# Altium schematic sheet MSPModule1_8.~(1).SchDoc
size 297 x 209 mm; PageSetup: Record=PageOptions¦CenterHorizontal=True¦CenterVertical=True¦PrintScale=0.99¦XCorrection=1.00¦YCorrection=1.00¦PrintKind=0¦BorderSize=5000000¦LeftOffset=0¦BottomOffset=0¦Orientation=2¦PaperLength=1000¦PaperWidth=1000¦Scale=100¦PaperSource=7¦PrintQuality=-3¦MediaType=1¦DitherType=10¦PrintScaleMode=1¦PaperKind=A4¦PaperIndex=9
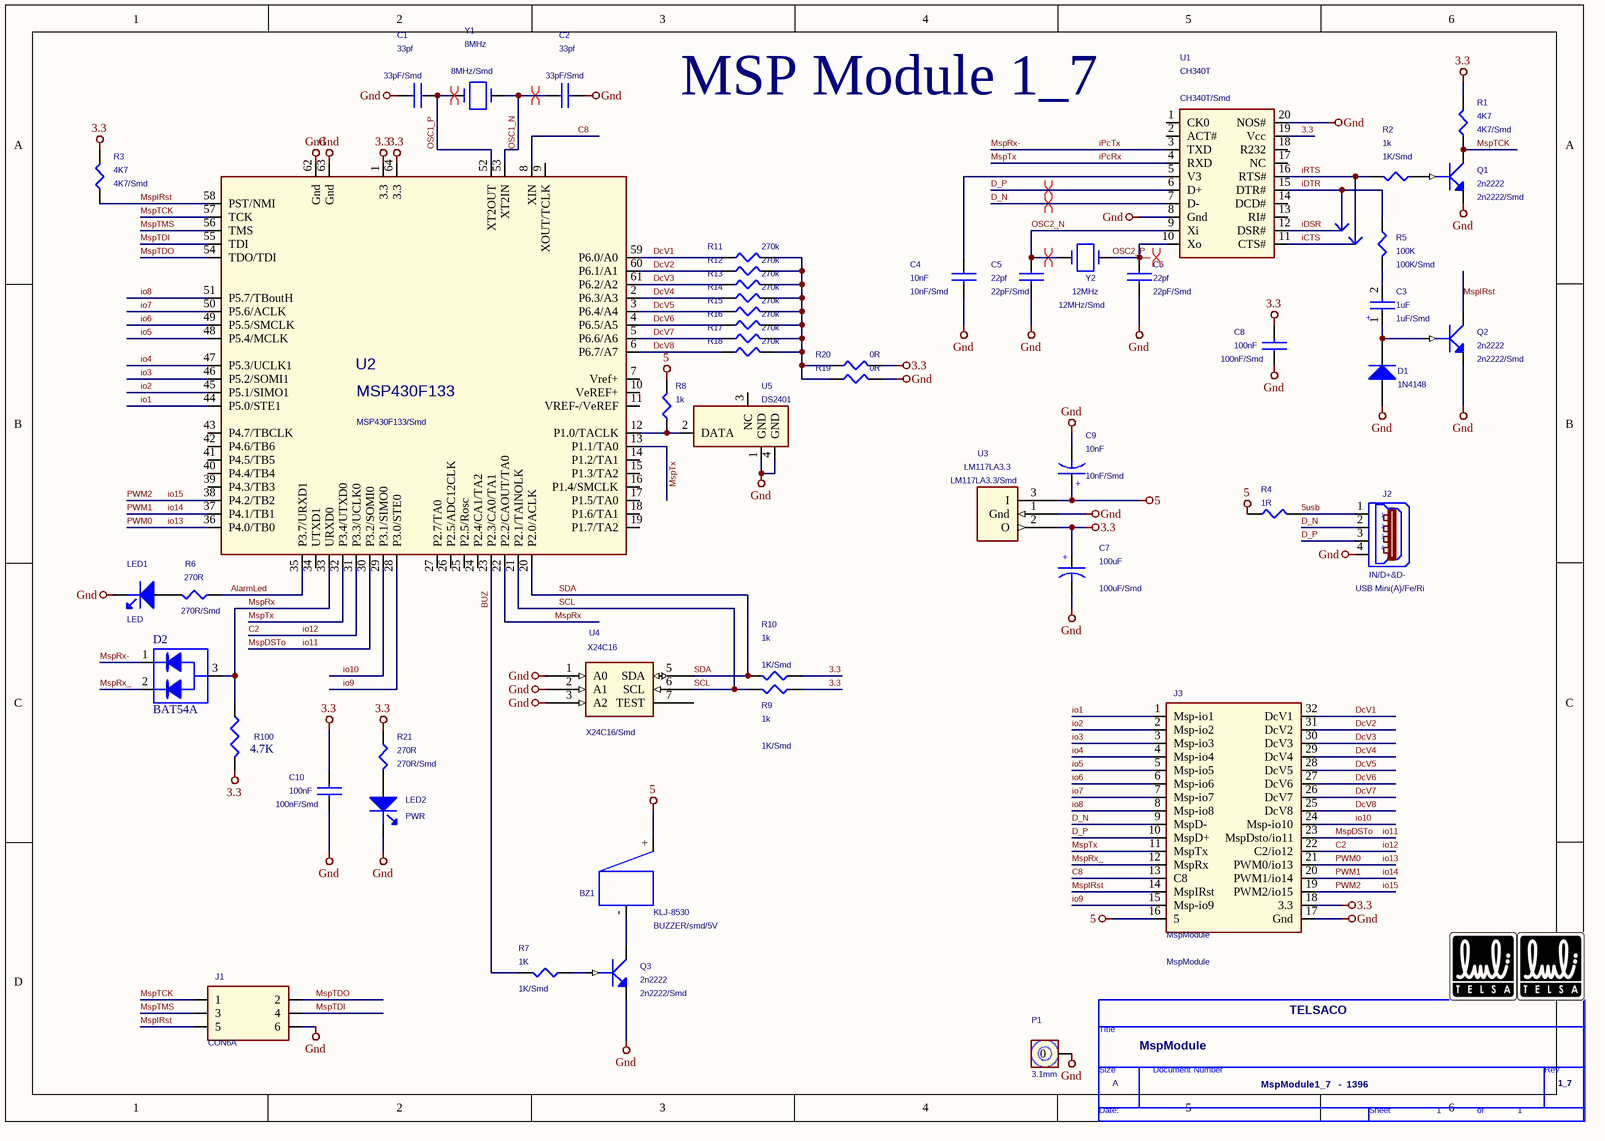
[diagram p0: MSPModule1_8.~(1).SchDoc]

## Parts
*  Page Count: 1  Page Size: A  Title: MspModule  RevCode: 1_7  Doc: MspModule1_7   -  1396  OrgName: TELSACO  (hidden comment: TitleBlock0)  (graphical)
BZ1  KLJ-8530  PART: BUZZER/smd/5V  [BUZZER SMD]
C1  33pf  PART: 33pF/Smd  [0805T]
C2  33pf  PART: 33pF/Smd  [0805T]
C3  1uF  PART: 1uF/Smd  [0805T]
C4  10nF  PART: 10nF/Smd  [0805T]
C5  22pf  PART: 22pF/Smd  [0805T]
C6  22pf  PART: 22pF/Smd  [0805T]
C7  100uF  PART: 100uF/Smd  [1210T]
C8  100nF  PART: 100nF/Smd  [0805T]
C9  10nF  PART: 10nF/Smd  [0805T]
C10  100nF  PART: 100nF/Smd  [0805T]
D1  1N4148  [0805-D]
D2  BAT54A  [SOT23]
J1  CON6A  [IDC6]
J2  IN/D+&D-  PART: USB Mini(A)/Fe/Ri  [MINI USB]
J3  MspModule  [MSPMODULE_2MM]
LED1  LED  [0805-D]
LED2  PWR  [0805-D]
P1  3.1mm  [SCREW3.1]
Q1  2n2222  PART: 2n2222/Smd  [SOT23_3]
Q2  2n2222  PART: 2n2222/Smd  [SOT23_3]
Q3  2n2222  PART: 2n2222/Smd  [SOT23_3]
R1  4K7  PART: 4K7/Smd  [0805R]
R2  1k  PART: 1K/Smd  [0805R]
R3  4K7  PART: 4K7/Smd  [0805R]
R4  1R  [0805R]
R5  100K  PART: 100K/Smd  [0805R]
R6  270R  PART: 270R/Smd  [0805R]
R7  1K  PART: 1K/Smd  [0805R]
R8  1k  [0805R]
R9  1k  PART: 1K/Smd  [0805R]
R10  1k  PART: 1K/Smd  [0805R]
R11  270k  [0805R]
R12  270k  [0805R]
R13  270k  [0805R]
R14  270k  [0805R]
R15  270k  [0805R]
R16  270k  [0805R]
R17  270k  [0805R]
R18  270k  [0805R]
R19  0R  [0805R]
R20  0R  [0805R]
R21  270R  PART: 270R/Smd  [0805R]
R100  4.7K  [0805R]
Telsa  ARM Telsa  [Arm2-Top]  (value not drawn)
Telsa1  ARM Telsa  [ARM1]  (value not drawn)
U1  CH340T  PART: CH340T/Smd  [SSOP20]
U2  MSP430F133  PART: MSP430F133/Smd  [MSP64]
U3  LM117LA3.3  PART: LM117LA3.3/Smd  [LM117]
U4  X24C16  PART: X24C16/Smd  [SO-8]
U5  DS2401  [DS2401]
Y1  8MHz  PART: 8MHz/Smd  [CRYSTAL-SMD]
Y2  12MHz  PART: 12MHz/Smd  [CRYSTAL-SMD]

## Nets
3.3: C7.1 C8.2 C10.2 J3.18(3.3) R1.2 R3.2 R9.1 R10.1 R20.2 R21.2 R100.2 U1.19(Vcc) U2.1(3.3) U2.64(3.3) U3.2(O) U4.8(3.3)
5: BZ1.+ C9.1 J3.16(5) R4.1 R8.2 U3.3(I)
Gnd: C1.2 C2.2 C4.2 C5.2 C6.2 C7.2 C8.1 C9.2 C10.1 D1.A J1.6 J2.4(GND) J2.5(GND) J3.17(Gnd) LED1.2 LED2.2 P1.0 Q1.2 Q2.2 Q3.2 R19.2 U1.8(Gnd) U1.20(NOS#) U2.62(Gnd) U2.63(Gnd) U3.1(Gnd) U4.1(A0) U4.2(A1) U4.3(A2) U4.4(Gnd) U5.1(GND) U5.4(GND)
5usb: J2.1(5V) R4.2
AlarmLed: R6.2 U2.35(P3.7/URXD1)
BUZ: R7.2 U2.23(P2.3/CA0/TA1)
C2: J3.22(C2/io12) U2.31(P3.3/UCLK0)  [also labelled io12]
C8: J3.13(C8) U2.8(XIN)
D_N: J2.2(D-) J3.9(MspD-) U1.7(D-)
D_P: J2.3(D+) J3.10(MspD+) U1.6(D+)
DcV1: J3.32(DcV1) R11.1 U2.59(P6.0/A0)
DcV2: J3.31(DcV2) R12.1 U2.60(P6.1/A1)
DcV3: J3.30(DcV3) R13.1 U2.61(P6.2/A2)
DcV4: J3.29(DcV4) R14.1 U2.2(P6.3/A3)
DcV5: J3.28(DcV5) R15.1 U2.3(P6.4/A4)
DcV6: J3.27(DcV6) R16.1 U2.4(P6.5/A5)
DcV7: J3.26(DcV7) R17.1 U2.5(P6.6/A6)
DcV8: J3.25(DcV8) R18.1 U2.6(P6.7/A7)
iCTS: R2.2 U1.11(CTS#) U1.16(RTS#)  [also labelled iRTS]
iDSR: R5.1 U1.12(DSR#) U1.15(DTR#)  [also labelled iDTR]
io1: J3.1(Msp-io1) U2.44(P5.0/STE1)
io2: J3.2(Msp-io2) U2.45(P5.1/SIMO1)
io3: J3.3(Msp-io3) U2.46(P5.2/SOMI1)
io4: J3.4(Msp-io4) U2.47(P5.3/UCLK1)
io5: J3.5(Msp-io5) U2.48(P5.4/MCLK)
io6: J3.6(Msp-io6) U2.49(P5.5/SMCLK)
io7: J3.7(Msp-io7) U2.50(P5.6/ACLK)
io8: J3.8(Msp-io8) U2.51(P5.7/TBoutH)
io9: J3.15(Msp-io9) U2.28(P3.0/STE0)
io10: J3.24(Msp-io10) U2.29(P3.1/SIMO0)
io11: J3.23(MspDsto/io11) U2.30(P3.2/SOMI0)  [also labelled MspDSTo]
io13: J3.21(PWM0/io13) U2.36(P4.0/TB0)  [also labelled PWM0]
io14: J3.20(PWM1/io14) U2.37(P4.1/TB1)  [also labelled PWM1]
io15: J3.19(PWM2/io15) U2.38(P4.2/TB2)  [also labelled PWM2]
iPcRx: J3.11(MspTx) U1.4(RXD) U2.13(P1.1/TA0) U2.32(P3.4/UTXD0)  [also labelled MspTx]
iPcTx: D2.1 U1.3(TXD)  [also labelled MspRx-]
MspIRst: J1.5 J3.14(MspIRst) Q2.3 R3.1 U2.58(PST/NMI)
MspRx: D2.3 R100.1 U2.22(P2.2/CAOUT/TA0) U2.33(URXD0)
MspRx_: D2.2 J3.12(MspRx)
MspTCK: J1.1 Q1.3 R1.1 U2.57(TCK)
MspTDI: J1.4 U2.55(TDI)
MspTDO: J1.2 U2.54(TDO/TDI)
MspTMS: J1.3 U2.56(TMS)
OSC1_N: C2.1 U2.53(XT2IN) Y1.1
OSC1_P: C1.1 U2.52(XT2OUT) Y1.2
OSC2_N: C5.1 U1.9(Xi) Y2.2
OSC2_P: C6.1 U1.10(Xo) Y2.1
SCL: R9.2 U2.21(P2.1/TAINOLK) U4.6(SCL)
SDA: R10.2 U2.20(P2.0/ACLK) U4.5(SDA)
NetBZ1_-: BZ1.- Q3.3
NetC3_1: C3.1(+) D1.K Q2.1
NetC3_2: C3.2(-) R5.2
NetC4_1: C4.1 U1.5(V3)
NetLED1_1: LED1.1 R6.1
NetLED2_1: LED2.1 R21.1
NetQ1_1: Q1.1 R2.1
NetQ3_1: Q3.1 R7.1
NetR8_1: R8.1 U2.12(P1.0/TACLK) U5.2(DATA)
NetR11_2: R11.2 R12.2 R13.2 R14.2 R15.2 R16.2 R17.2 R18.2 R19.1 R20.1

Not connected (* = marked no-connect by the designer): U1 1(CK0) 2(ACT#) 13(RI#) 14(DCD#) 17(NC) 18(R232); U2 7(Vref+) 9(XOUT/TCLK) 10(VeREF+) 11(VREF-/VeREF) 14(P1.2/TA1) 15(P1.3/TA2) 16(P1.4/SMCLK) 17(P1.5/TA0) 18(P1.6/TA1) 19(P1.7/TA2) 24(P2.4/CA1/TA2) 25(P2.5/Rosc) 26(P2.5/ADC12CLK) 27(P2.7/TA0) 34(UTXD1) 39(P4.3/TB3) 40(P4.4/TB4) 41(P4.5/TB5) 42(P4.6/TB6) 43(P4.7/TBCLK); U4 7(TEST); U5 3(NC)

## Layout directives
differential pair: D_N, D_P, OSC1_N, OSC1_P, OSC2_N, OSC2_P

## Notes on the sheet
- MSP Module 1_7

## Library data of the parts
BZ1 = BUZZER_0: Buzzer
C1 C2 C4-C6 = CAP NP_Dup2: Capacitor
C3 = CAP NP_1: Capacitor
C7 C9 = CAP_1: Capacitor
C8 C10 = CAP NP_Dup1: Capacitor
D1 = Diode
J1 = CON4A_0: Header 2*3 Male
J2 = 4N49_8: USB Connector
J3 = CON14_16
LED1 = LED_2
LED2 = LED_2: LED
P1 = Screw
Q1-Q3 = NPN_4: NPN Transistor
R1-R3 R5-R7 R9 R10 R21 = R_0_Dup2: Resistor
R4 R8 R11-R18 = R_0_Dup2: Resistor; PART: 270K/Smd
R19 R20 = R_0_Dup2: Resistor; PART: 0R/Smd
R100 = RES_SMD_0805
Telsa Telsa1 = ARM Tellsa
U1 = CON20A_2: USB to Serial chip
U2 = CON89_1: 16-bit Microcontroller
U3 = LM117LA_0: Regulator
U4 = X24C16_1: Serial E2PROM
U5 = CON4A_3: Silicon Serial Number
Y1 Y2 = CRYSTAL: Crystal Oscillator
